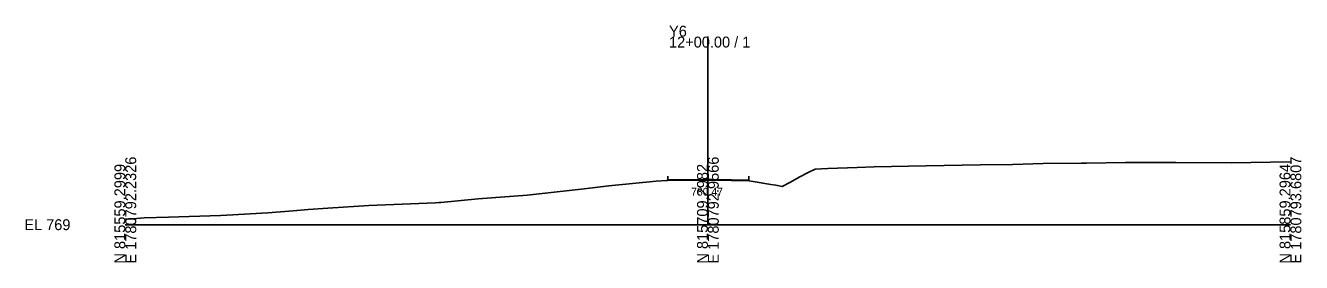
# Model space of a CAD drawing. Extents: x -26 to 1603, y -10 to 6024.
# Drawn here: x -25.7 to 302.8, y 1990.3 to 2051.1 of the extents above; entities that cross this region are included whole.
import ezdxf

# ---------------------------------------------------------------- set-up
doc = ezdxf.new("R2010")
doc.units = 0
for name, color, linetype in [('Exist Cross Section Cell', 7, 'Continuous'), ('Exist XS Center Line Elevation Label', 7, 'Continuous'), ('Exist XS Ground Line', 7, 'Continuous'), ('Prop XS EOT Tick Mark', 7, 'Continuous'), ('Prop XS Finish Grade Pavement', 7, 'Continuous')]:
    doc.layers.add(name, color=color, linetype=linetype)

msp = doc.modelspace()

# ---------------------------------------------------------------- linework, layer by layer
at = {"layer": 'Exist Cross Section Cell'}
for p, q in [((150, 2000), (150, 2048.3)), ((0, 2000), (150, 2000)), ((150, 2000), (300, 2000))]:
    msp.add_line(p, q, dxfattribs=at)
at = {"layer": 'Exist XS Ground Line'}
for p, q in [((175.79, 2013.42), (177.61, 2014.22)), ((177.61, 2014.22), (180.92, 2014.41)), ((180.92, 2014.41), (188.47, 2014.7)), ((188.47, 2014.7), (192.82, 2014.86)), ((192.82, 2014.86), (206.12, 2015.12)), ((206.12, 2015.12), (220.2, 2015.34)), ((220.2, 2015.34), (228.45, 2015.48)), ((228.45, 2015.48), (236.31, 2015.71)), ((236.31, 2015.71), (246.22, 2015.82)), ((246.22, 2015.82), (246.95, 2015.83)), ((246.95, 2015.83), (247.52, 2015.84)), ((247.52, 2015.84), (257.57, 2015.98)), ((257.57, 2015.98), (266.42, 2016)), ((266.42, 2016), (268.15, 2015.94)), ((268.15, 2015.94), (270.49, 2015.94)), ((270.49, 2015.94), (284.76, 2015.92)), ((284.76, 2015.92), (294.9, 2016.02)), ((294.9, 2016.02), (300, 2016.1)), ((124.47, 2009.94), (136.7, 2011.14)), ((136.7, 2011.14), (139.31, 2011.35)), ((139.31, 2011.35), (139.68, 2011.37)), ((139.68, 2011.37), (145.12, 2011.42)), ((145.12, 2011.42), (150.22, 2011.47)), ((150.22, 2011.47), (156.06, 2011.37)), ((156.06, 2011.37), (160.55, 2011.3)), ((160.55, 2011.3), (161.65, 2011.1)), ((161.65, 2011.1), (166.2, 2010.31)), ((169.15, 2009.78), (171.06, 2010.84)), ((171.06, 2010.84), (173.67, 2012.32)), ((173.67, 2012.32), (175.79, 2013.42)), ((90.89, 2006.66), (103.45, 2007.59)), ((103.45, 2007.59), (118.18, 2009.23)), ((118.18, 2009.23), (124.47, 2009.94)), ((166.2, 2010.31), (167.46, 2010.14)), ((167.46, 2010.14), (169.15, 2009.78)), ((47.04, 2003.86), (52.12, 2004.24)), ((52.12, 2004.24), (62.67, 2004.93)), ((62.67, 2004.93), (79.88, 2005.64)), ((79.88, 2005.64), (80.84, 2005.69)), ((80.84, 2005.69), (81.24, 2005.71)), ((81.24, 2005.71), (90.89, 2006.66)), ((0, 2001.41), (2.06, 2001.52)), ((2.06, 2001.52), (4.84, 2001.75)), ((4.84, 2001.75), (11.15, 2001.97)), ((11.15, 2001.97), (24.54, 2002.35)), ((24.54, 2002.35), (26.14, 2002.42)), ((26.14, 2002.42), (36.72, 2003.08)), ((36.72, 2003.08), (43.26, 2003.55)), ((43.26, 2003.55), (47.04, 2003.86))]:
    msp.add_line(p, q, dxfattribs=at)
at = {"layer": 'Prop XS EOT Tick Mark'}
for p, q in [((139.68, 2011.5), (139.68, 2012.5)), ((160.55, 2011.43), (160.55, 2012.43))]:
    msp.add_line(p, q, dxfattribs=at)
at = {"layer": 'Prop XS Finish Grade Pavement'}
for p, q in [((139.68, 2011.5), (145.12, 2011.55)), ((145.12, 2011.55), (150.21, 2011.6)), ((150.22, 2011.6), (156.06, 2011.5)), ((156.06, 2011.5), (160.55, 2011.43))]:
    msp.add_line(p, q, dxfattribs=at)

# ---------------------------------------------------------------- texts
at = {"layer": 'Exist Cross Section Cell'}
for s, p in [('Y6', (140, 2048.3)), ('12+00.00 / 1', (140, 2045.5)), ('EL 769', (-26, 1998.6))]:
    msp.add_text(s, height=2.8, dxfattribs=at).set_placement(p)
for s, p in [('E 1780792.2326', (2.8, 1990)), ('E 1780792.9566', (152.8, 1990)), ('E 1780793.6807', (302.8, 1990)), ('N 815559.2999', (0, 1990)), ('N 815709.2982', (150, 1990)), ('N 815859.2964', (300, 1990))]:
    msp.add_text(s, height=2.8, rotation=90, dxfattribs=at).set_placement(p)
at = {"layer": 'Exist XS Center Line Elevation Label'}
msp.add_text('780.47', height=2, dxfattribs=at).set_placement((145.7, 2007.47))

doc.saveas('drawing.dxf')
